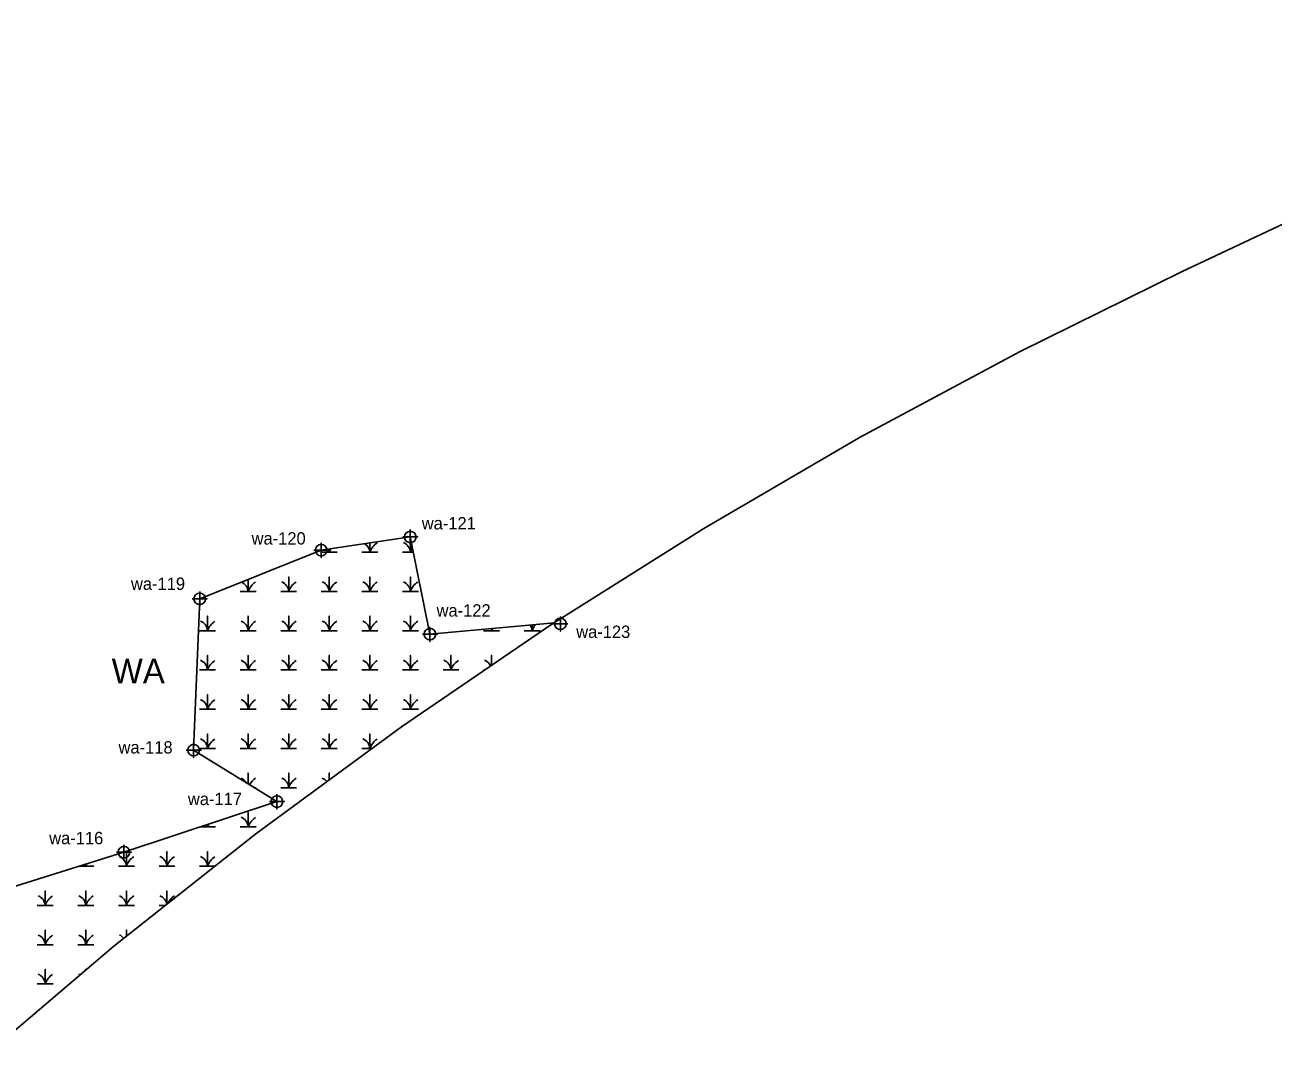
# Model space of a CAD drawing. Extents: x 2379288 to 2381905, y 330670 to 333511.
# Drawn here: x 2380893 to 2381399, y 332572 to 332993 of the extents above; entities that cross this region are included whole.
import ezdxf

# ---------------------------------------------------------------- set-up
doc = ezdxf.new("R2010")
doc.units = 0
for name, color, linetype in [('Default', 7, 'Continuous'), ('Exist Environmental Wetland Boundary', 7, 'Continuous'), ('Exist Environmental Wetland Boundary Cogo Number', 7, 'Continuous'), ('Exist Environmental Wetland Boundary Cogo Point CELL', 7, 'Continuous'), ('Exist Environmental Wetland Boundary Text', 7, 'Continuous'), ('Exist Hydro Swamp or Marsh', 7, 'Continuous')]:
    doc.layers.add(name, color=color, linetype=linetype)

msp = doc.modelspace()

# ---------------------------------------------------------------- linework, layer by layer
at = {"layer": 'Default'}
msp.add_lwpolyline([(2380850.96, 333060.51), (2380916.47, 333103.65), (2380983.3, 333144.71), (2381051.4, 333183.64), (2381120.69, 333220.4), (2381191.11, 333254.95), (2381734.22, 333510.92), (2381904.75, 333149.09), (2381361.64, 332893.12), (2381295.86, 332860.7), (2381231.27, 332825.99), (2381167.94, 332789.02), (2381105.95, 332749.86), (2381045.37, 332708.54), (2380986.28, 332665.11), (2380928.76, 332619.64), (2380872.86, 332572.17)], dxfattribs=at)
at = {"layer": 'Exist Environmental Wetland Boundary'}
msp.add_lwpolyline([(2380837.85, 332627.97), (2380932.82, 332657.69), (2380994.86, 332678.22), (2380961.08, 332699.06), (2380963.55, 332760.47), (2381012.8, 332780.2), (2381048.93, 332785.56), (2381056.91, 332746.13), (2381107.36, 332750.75)], dxfattribs=at)
at = {"layer": 'Exist Environmental Wetland Boundary Cogo Point CELL'}
for points in [[(2381048.93, 332788.56), (2381048.93, 332782.56), (2381048.93, 332785.56), (2381051.93, 332785.56), (2381045.93, 332785.56)], [(2381012.8, 332783.2), (2381012.8, 332777.2), (2381012.8, 332780.2), (2381015.8, 332780.2), (2381009.8, 332780.2)], [(2380963.55, 332763.47), (2380963.55, 332757.47), (2380963.55, 332760.47), (2380966.55, 332760.47), (2380960.55, 332760.47)], [(2381109.78, 332753.33), (2381109.78, 332747.33), (2381109.78, 332750.33), (2381112.78, 332750.33), (2381106.78, 332750.33)], [(2381056.91, 332749.13), (2381056.91, 332743.13), (2381056.91, 332746.13), (2381059.91, 332746.13), (2381053.91, 332746.13)], [(2380961.08, 332702.06), (2380961.08, 332696.06), (2380961.08, 332699.06), (2380964.08, 332699.06), (2380958.08, 332699.06)], [(2380994.86, 332681.22), (2380994.86, 332675.22), (2380994.86, 332678.22), (2380997.86, 332678.22), (2380991.86, 332678.22)], [(2380932.82, 332660.69), (2380932.82, 332654.69), (2380932.82, 332657.69), (2380935.82, 332657.69), (2380929.82, 332657.69)]]:
    msp.add_lwpolyline(points, dxfattribs=at)
for centre in [(2381048.93, 332785.56), (2381012.8, 332780.2), (2380963.55, 332760.47), (2381056.91, 332746.13), (2381109.78, 332750.33), (2380961.08, 332699.06), (2380994.86, 332678.22), (2380932.82, 332657.69)]:
    msp.add_circle(centre, 2.34, dxfattribs=at)
at = {"layer": 'Exist Hydro Swamp or Marsh'}
for p, q in [((2381078.66, 332731.61), (2381079.2, 332731.61)), ((2380985.72, 332683.86), (2380986.4, 332683.86)), ((2380947.05, 332636.1), (2380949.67, 332636.1))]:
    msp.add_line(p, q, dxfattribs=at)
for points in [[(2381045.76, 332779.36), (2381048.98, 332779.36), (2381048.98, 332785.28), (2381048.98, 332779.36), (2381050.19, 332779.36)], [(2381012.85, 332779.36), (2381016.08, 332779.36), (2381016.08, 332780.69)], [(2381016.08, 332780.69), (2381016.08, 332779.36), (2381019.31, 332779.36)], [(2381029.31, 332779.36), (2381032.53, 332779.36), (2381032.53, 332783.12)], [(2381032.53, 332783.12), (2381032.53, 332779.36), (2381035.76, 332779.36)], [(2380979.95, 332763.45), (2380983.18, 332763.45), (2380983.18, 332768.33)], [(2380983.18, 332768.33), (2380983.18, 332763.45), (2380986.4, 332763.45)], [(2380996.4, 332763.45), (2380999.63, 332763.45), (2380999.63, 332769.36), (2380999.63, 332763.45), (2381002.85, 332763.45)], [(2381012.85, 332763.45), (2381016.08, 332763.45), (2381016.08, 332769.36), (2381016.08, 332763.45), (2381019.31, 332763.45)], [(2381029.31, 332763.45), (2381032.53, 332763.45), (2381032.53, 332769.36), (2381032.53, 332763.45), (2381035.76, 332763.45)], [(2381045.76, 332763.45), (2381048.98, 332763.45), (2381048.98, 332769.36), (2381048.98, 332763.45), (2381052.21, 332763.45)], [(2380963.5, 332747.53), (2380966.73, 332747.53), (2380966.73, 332753.45), (2380966.73, 332747.53), (2380969.95, 332747.53)], [(2380979.95, 332747.53), (2380983.18, 332747.53), (2380983.18, 332753.45), (2380983.18, 332747.53), (2380986.4, 332747.53)], [(2380996.4, 332747.53), (2380999.63, 332747.53), (2380999.63, 332753.45), (2380999.63, 332747.53), (2381002.85, 332747.53)], [(2381012.85, 332747.53), (2381016.08, 332747.53), (2381016.08, 332753.45), (2381016.08, 332747.53), (2381019.31, 332747.53)], [(2381029.31, 332747.53), (2381032.53, 332747.53), (2381032.53, 332753.45), (2381032.53, 332747.53), (2381035.76, 332747.53)], [(2381045.76, 332747.53), (2381048.98, 332747.53), (2381048.98, 332753.45), (2381048.98, 332747.53), (2381052.21, 332747.53)], [(2381078.66, 332747.53), (2381081.88, 332747.53), (2381081.88, 332748.42)], [(2381081.88, 332748.42), (2381081.88, 332747.53), (2381085.11, 332747.53)], [(2381095.11, 332747.53), (2381098.34, 332747.53), (2381098.34, 332749.92)], [(2381098.34, 332749.92), (2381098.34, 332747.53), (2381101.56, 332747.53)], [(2380963.5, 332731.61), (2380966.73, 332731.61), (2380966.73, 332737.53), (2380966.73, 332731.61), (2380969.95, 332731.61)], [(2380979.95, 332731.61), (2380983.18, 332731.61), (2380983.18, 332737.53), (2380983.18, 332731.61), (2380986.4, 332731.61)], [(2380996.4, 332731.61), (2380999.63, 332731.61), (2380999.63, 332737.53), (2380999.63, 332731.61), (2381002.85, 332731.61)], [(2381012.85, 332731.61), (2381016.08, 332731.61), (2381016.08, 332737.53), (2381016.08, 332731.61), (2381019.31, 332731.61)], [(2381029.31, 332731.61), (2381032.53, 332731.61), (2381032.53, 332737.53), (2381032.53, 332731.61), (2381035.76, 332731.61)], [(2381045.76, 332731.61), (2381048.98, 332731.61), (2381048.98, 332737.53), (2381048.98, 332731.61), (2381052.21, 332731.61)], [(2381062.21, 332731.61), (2381065.43, 332731.61), (2381065.43, 332737.53), (2381065.43, 332731.61), (2381068.66, 332731.61)], [(2381081.88, 332733.44), (2381081.88, 332737.53), (2381081.88, 332733.44)], [(2380963.5, 332715.69), (2380966.73, 332715.69), (2380966.73, 332721.61), (2380966.73, 332715.69), (2380969.95, 332715.69)], [(2380979.95, 332715.69), (2380983.18, 332715.69), (2380983.18, 332721.61), (2380983.18, 332715.69), (2380986.4, 332715.69)], [(2380996.4, 332715.69), (2380999.63, 332715.69), (2380999.63, 332721.61), (2380999.63, 332715.69), (2381002.85, 332715.69)], [(2381012.85, 332715.69), (2381016.08, 332715.69), (2381016.08, 332721.61), (2381016.08, 332715.69), (2381019.31, 332715.69)], [(2381029.31, 332715.69), (2381032.53, 332715.69), (2381032.53, 332721.61), (2381032.53, 332715.69), (2381035.76, 332715.69)], [(2381045.76, 332715.69), (2381048.98, 332715.69), (2381048.98, 332721.61), (2381048.98, 332715.69), (2381052.21, 332715.69)], [(2380963.5, 332699.77), (2380966.73, 332699.77), (2380966.73, 332705.69), (2380966.73, 332699.77), (2380969.95, 332699.77)], [(2380979.95, 332699.77), (2380983.18, 332699.77), (2380983.18, 332705.69), (2380983.18, 332699.77), (2380986.4, 332699.77)], [(2380996.4, 332699.77), (2380999.63, 332699.77), (2380999.63, 332705.69), (2380999.63, 332699.77), (2381002.85, 332699.77)], [(2381012.85, 332699.77), (2381016.08, 332699.77), (2381016.08, 332705.69), (2381016.08, 332699.77), (2381019.31, 332699.77)], [(2381029.31, 332699.77), (2381032.53, 332699.77), (2381032.53, 332705.69), (2381032.53, 332699.77), (2381033.45, 332699.77)], [(2380983.18, 332685.43), (2380983.18, 332689.77), (2380983.18, 332685.43)], [(2380996.4, 332683.86), (2380999.63, 332683.86), (2380999.63, 332689.77), (2380999.63, 332683.86), (2381002.85, 332683.86)], [(2381016.08, 332687.01), (2381016.08, 332689.77), (2381016.08, 332687.01)], [(2380979.95, 332667.94), (2380983.18, 332667.94), (2380983.18, 332673.86), (2380983.18, 332667.94), (2380986.4, 332667.94)], [(2380963.8, 332667.94), (2380966.73, 332667.94), (2380966.73, 332668.91)], [(2380966.73, 332668.91), (2380966.73, 332667.94), (2380969.95, 332667.94)], [(2380930.6, 332652.02), (2380933.82, 332652.02), (2380933.82, 332657.94), (2380933.82, 332652.02), (2380937.05, 332652.02)], [(2380947.05, 332652.02), (2380950.28, 332652.02), (2380950.28, 332657.94), (2380950.28, 332652.02), (2380953.5, 332652.02)], [(2380963.5, 332652.02), (2380966.73, 332652.02), (2380966.73, 332657.94), (2380966.73, 332652.02), (2380969.72, 332652.02)], [(2380914.71, 332652.02), (2380917.37, 332652.02), (2380917.37, 332652.85)], [(2380917.37, 332652.85), (2380917.37, 332652.02), (2380920.6, 332652.02)], [(2380897.7, 332636.1), (2380900.92, 332636.1), (2380900.92, 332642.02), (2380900.92, 332636.1), (2380904.15, 332636.1)], [(2380914.15, 332636.1), (2380917.37, 332636.1), (2380917.37, 332642.02), (2380917.37, 332636.1), (2380920.6, 332636.1)], [(2380930.6, 332636.1), (2380933.82, 332636.1), (2380933.82, 332642.02), (2380933.82, 332636.1), (2380937.05, 332636.1)], [(2380950.28, 332636.58), (2380950.28, 332642.02), (2380950.28, 332636.58)], [(2380897.7, 332620.19), (2380900.92, 332620.19), (2380900.92, 332626.1), (2380900.92, 332620.19), (2380904.15, 332620.19)], [(2380914.15, 332620.19), (2380917.37, 332620.19), (2380917.37, 332626.1), (2380917.37, 332620.19), (2380920.6, 332620.19)], [(2380933.82, 332623.51), (2380933.82, 332626.1), (2380933.82, 332623.51)], [(2380897.7, 332604.27), (2380900.92, 332604.27), (2380900.92, 332610.19), (2380900.92, 332604.27), (2380904.15, 332604.27)], [(2380917.37, 332609.97), (2380917.37, 332610.19), (2380917.37, 332609.97)]]:
    msp.add_lwpolyline(points, dxfattribs=at)
for centre, radius, start, end in [((2381011.48, 332779.03), 4.61, 4.1403, 20.5022), ((2381022.92, 332777.09), 7.21, 149.1834, 161.6222), ((2381027.93, 332779.03), 4.61, 4.1403, 55.484), ((2381039.37, 332777.09), 7.21, 122.1274, 161.6222), ((2381044.38, 332779.03), 4.61, 4.1403, 67.535), ((2381055.82, 332777.09), 7.21, 146.1677, 161.6222), ((2380978.58, 332763.11), 4.61, 4.1403, 64.6297), ((2380990.02, 332761.17), 7.21, 122.1274, 161.6222), ((2380995.03, 332763.11), 4.61, 4.1403, 67.535), ((2381006.47, 332761.17), 7.21, 122.1274, 161.6222), ((2381011.48, 332763.11), 4.61, 4.1403, 67.535), ((2381022.92, 332761.17), 7.21, 122.1274, 161.6222), ((2381027.93, 332763.11), 4.61, 4.1403, 67.535), ((2381039.37, 332761.17), 7.21, 122.1274, 161.6222), ((2381044.38, 332763.11), 4.61, 4.1403, 67.535), ((2381055.82, 332761.17), 7.21, 122.1274, 161.6222), ((2380962.13, 332747.2), 4.61, 4.1403, 67.535), ((2380973.57, 332745.26), 7.21, 122.1274, 161.6222), ((2380978.58, 332747.2), 4.61, 4.1403, 67.535), ((2380990.02, 332745.26), 7.21, 122.1274, 161.6222), ((2380995.03, 332747.2), 4.61, 4.1403, 67.535), ((2381006.47, 332745.26), 7.21, 122.1274, 161.6222), ((2381011.48, 332747.2), 4.61, 4.1403, 67.535), ((2381022.92, 332745.26), 7.21, 122.1274, 161.6222), ((2381027.93, 332747.2), 4.61, 4.1403, 67.535), ((2381039.37, 332745.26), 7.21, 122.1274, 161.6222), ((2381044.38, 332747.2), 4.61, 4.1403, 67.535), ((2381055.82, 332745.26), 7.21, 122.1274, 161.6222), ((2381077.28, 332747.2), 4.61, 4.1403, 15.2168), ((2381088.73, 332745.26), 7.21, 153.6565, 161.6222), ((2381093.74, 332747.2), 4.61, 4.1403, 35.1317), ((2381105.18, 332745.26), 7.21, 138.2112, 161.6222), ((2380962.13, 332731.28), 4.61, 4.1403, 67.535), ((2380973.57, 332729.34), 7.21, 122.1274, 161.6222), ((2380978.58, 332731.28), 4.61, 4.1403, 67.535), ((2380990.02, 332729.34), 7.21, 122.1274, 161.6222), ((2380995.03, 332731.28), 4.61, 4.1403, 67.535), ((2381006.47, 332729.34), 7.21, 122.1274, 161.6222), ((2381011.48, 332731.28), 4.61, 4.1403, 67.535), ((2381022.92, 332729.34), 7.21, 122.1274, 161.6222), ((2381027.93, 332731.28), 4.61, 4.1403, 67.535), ((2381039.37, 332729.34), 7.21, 122.1274, 161.6222), ((2381044.38, 332731.28), 4.61, 4.1403, 67.535), ((2381055.82, 332729.34), 7.21, 122.1274, 161.6222), ((2381060.83, 332731.28), 4.61, 4.1403, 67.535), ((2381072.27, 332729.34), 7.21, 122.1274, 161.6222), ((2381077.28, 332731.28), 4.61, 24.2659, 67.535), ((2380962.13, 332715.36), 4.61, 4.1403, 67.535), ((2380973.57, 332713.42), 7.21, 122.1274, 161.6222), ((2380978.58, 332715.36), 4.61, 4.1403, 67.535), ((2380990.02, 332713.42), 7.21, 122.1274, 161.6222), ((2380995.03, 332715.36), 4.61, 4.1403, 67.535), ((2381006.47, 332713.42), 7.21, 122.1274, 161.6222), ((2381011.48, 332715.36), 4.61, 4.1403, 67.535), ((2381022.92, 332713.42), 7.21, 122.1274, 161.6222), ((2381027.93, 332715.36), 4.61, 4.1403, 67.535), ((2381039.37, 332713.42), 7.21, 122.1274, 161.6222), ((2381044.38, 332715.36), 4.61, 4.1403, 67.535), ((2381055.82, 332713.42), 7.21, 122.1274, 161.6222), ((2380962.13, 332699.44), 4.61, 4.1403, 67.535), ((2380973.57, 332697.5), 7.21, 122.1274, 161.6222), ((2380978.58, 332699.44), 4.61, 4.1403, 67.535), ((2380990.02, 332697.5), 7.21, 122.1274, 161.6222), ((2380995.03, 332699.44), 4.61, 4.1403, 67.535), ((2381006.47, 332697.5), 7.21, 122.1274, 161.6222), ((2381011.48, 332699.44), 4.61, 4.1403, 67.535), ((2381022.92, 332697.5), 7.21, 122.1274, 161.6222), ((2381027.93, 332699.44), 4.61, 4.1403, 67.535), ((2381039.37, 332697.5), 7.21, 122.1274, 161.6222), ((2380978.58, 332683.52), 4.61, 29.3567, 67.535), ((2380990.02, 332681.58), 7.21, 122.1274, 150.8844), ((2380995.03, 332683.52), 4.61, 4.1403, 67.535), ((2381006.47, 332681.58), 7.21, 122.1274, 161.6222), ((2381011.48, 332683.52), 4.61, 37.3719, 67.535), ((2380962.13, 332667.61), 4.61, 4.1403, 15.7097), ((2380973.57, 332665.67), 7.21, 151.8376, 161.6222), ((2380978.58, 332667.61), 4.61, 4.1403, 67.535), ((2380990.02, 332665.67), 7.21, 122.1274, 161.6222), ((2380912.77, 332651.69), 4.61, 4.1403, 14.1322), ((2380924.21, 332649.75), 7.21, 153.3815, 161.6222), ((2380929.22, 332651.69), 4.61, 4.1403, 67.535), ((2380940.66, 332649.75), 7.21, 122.1274, 161.6222), ((2380945.68, 332651.69), 4.61, 4.1403, 67.535), ((2380957.12, 332649.75), 7.21, 122.1274, 161.6222), ((2380962.13, 332651.69), 4.61, 4.1403, 67.535), ((2380973.57, 332649.75), 7.21, 122.1274, 161.6222), ((2380896.32, 332635.77), 4.61, 4.1403, 67.535), ((2380907.76, 332633.83), 7.21, 122.1274, 161.6222), ((2380912.77, 332635.77), 4.61, 4.1403, 67.535), ((2380924.21, 332633.83), 7.21, 122.1274, 161.6222), ((2380929.22, 332635.77), 4.61, 4.1403, 67.535), ((2380940.66, 332633.83), 7.21, 122.1274, 161.6222), ((2380945.68, 332635.77), 4.61, 9.5955, 67.535), ((2380957.12, 332633.83), 7.21, 122.1274, 155.7119), ((2380896.32, 332619.85), 4.61, 4.1403, 67.535), ((2380907.76, 332617.91), 7.21, 122.1274, 161.6222), ((2380912.77, 332619.85), 4.61, 4.1403, 67.535), ((2380924.21, 332617.91), 7.21, 122.1274, 161.6222), ((2380929.22, 332619.85), 4.61, 38.4888, 67.535), ((2380896.32, 332603.94), 4.61, 4.1403, 67.535), ((2380907.76, 332602), 7.21, 122.1274, 161.6222), ((2380912.77, 332603.94), 4.61, 60.937, 67.535)]:
    msp.add_arc(centre, radius, start, end, dxfattribs=at)

# ---------------------------------------------------------------- texts
at = {"layer": 'Exist Environmental Wetland Boundary Cogo Number'}
for s, p in [('wa-121', (2381053.58, 332788.62)), ('wa-120', (2380984.59, 332782.49)), ('wa-119', (2380935.68, 332764.1)), ('wa-122', (2381059.58, 332753.28)), ('wa-123', (2381116.19, 332744.62)), ('wa-118', (2380930.63, 332697.73)), ('wa-117', (2380958.75, 332676.81)), ('wa-116', (2380902.51, 332660.94))]:
    msp.add_text(s, height=5, dxfattribs=at).set_placement(p)
at = {"layer": 'Exist Environmental Wetland Boundary Text'}
msp.add_text('WA', height=10, dxfattribs=at).set_placement((2380927.86, 332726.18))

doc.saveas('drawing.dxf')
